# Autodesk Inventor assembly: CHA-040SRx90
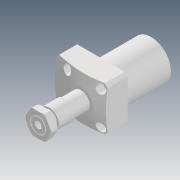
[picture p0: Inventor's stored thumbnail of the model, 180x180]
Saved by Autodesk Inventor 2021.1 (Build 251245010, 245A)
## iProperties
Created: 2019-05
Part Number: CHA-040SRx90
Description: STEP AP203
Document SubType Name: Assembly
Designer: user
Title: CHA-040SRx90.STEP
Revision Number: ÈÎºÎ
Sending System: SolidWorks 2017
Preprocessor: SwSTEP 2.0
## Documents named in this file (5)
- D:\Vault_2016\Projekty\Clamptek\Hydraulic\CHA\CHA\CHA-040\Inventor\CHA-040SRx90\CHA-040SRx90.iam
- D:\Vault_2016\Projekty\Clamptek\Hydraulic\CHA\CHA\CHA-040\Inventor\CHA-040SRx90\CHA-040±¾Ìå.ipt
- D:\Vault_2016\Projekty\Clamptek\Hydraulic\CHA\CHA\CHA-040\Inventor\CHA-040SRx90\CHA-040S»îÈû¸Ë.ipt
- D:\Vault_2016\Projekty\Clamptek\Hydraulic\CHA\CHA\CHA-040\Inventor\CHA-040SRx90\CHA-040S×¶Ì×.ipt
- D:\Vault_2016\Projekty\Clamptek\Hydraulic\CHA\CHA\CHA-040\Inventor\CHA-040SRx90\CHA-040ÂÝÄ¸.ipt
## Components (4 placed, 4 different names)
1. CHA-040±¾Ìå_1
2. CHA-040S»îÈû¸Ë_2
3. CHA-040S×¶Ì×_3
4. CHA-040ÂÝÄ¸_4
